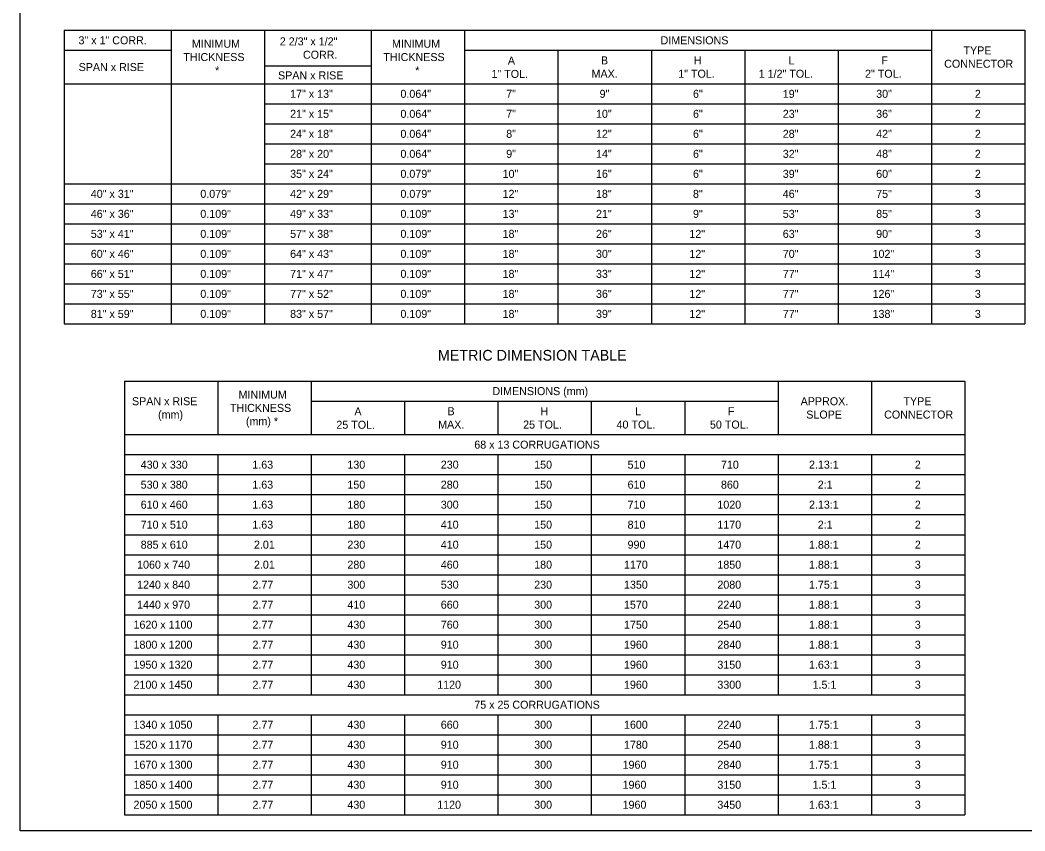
# Model space of a CAD drawing. Extents: x 49991.4 to 50021, y 49987.6 to 50011.4.
# Drawn here: x 49999.38 to 50006.92, y 49987.8 to 49993.88 of the extents above; entities that cross this region are included whole.
import ezdxf

# ---------------------------------------------------------------- set-up
doc = ezdxf.new("R2010")
doc.units = 0
doc.layers.add('Level 1', color=7, linetype='Continuous')
doc.layers.add('Level 2', color=7, linetype='Continuous')

msp = doc.modelspace()

# ---------------------------------------------------------------- linework, layer by layer
at = {"layer": 'Level 1'}
msp.add_lwpolyline([(49999.3835, 49998.9992), (50016.7501, 49998.9992), (50016.7501, 49987.7988), (49999.3835, 49987.7988)], close=True, dxfattribs=at)
at = {"layer": 'Level 2'}
for p, q in [((49999.715, 49993.802), (50006.915, 49993.802)), ((49999.715, 49993.802), (50006.915, 49993.802)), ((49999.715, 49993.802), (49999.715, 49991.6007)), ((50000.515, 49993.802), (50000.515, 49991.6007)), ((50001.215, 49993.802), (50001.215, 49991.6007)), ((50002.015, 49993.802), (50002.015, 49991.6007)), ((50002.715, 49993.802), (50002.715, 49993.2507)), ((50002.715, 49993.802), (50002.715, 49993.2507)), ((50006.215, 49993.802), (50006.215, 49993.2507)), ((50006.215, 49993.802), (50006.215, 49993.2507)), ((50006.915, 49993.802), (50006.915, 49993.402)), ((50006.915, 49993.802), (50006.915, 49993.402)), ((50006.915, 49993.802), (50006.915, 49991.6007)), ((49999.715, 49993.652), (50000.515, 49993.652)), ((50002.715, 49993.652), (50006.215, 49993.652)), ((50003.415, 49993.652), (50003.415, 49993.402)), ((50003.415, 49993.652), (50003.415, 49993.402)), ((50004.115, 49993.652), (50004.115, 49993.402)), ((50004.115, 49993.652), (50004.115, 49993.402)), ((50004.815, 49993.652), (50004.815, 49993.2507)), ((50004.815, 49993.652), (50004.815, 49993.2507)), ((50005.515, 49993.652), (50005.515, 49993.402)), ((50005.515, 49993.652), (50005.515, 49993.402)), ((50001.215, 49993.5351), (50002.015, 49993.5351)), ((49999.715, 49993.4007), (50006.915, 49993.4007)), ((49999.715, 49993.4007), (50006.915, 49993.4007)), ((50003.415, 49993.4007), (50003.415, 49991.6007)), ((50004.115, 49993.4007), (50004.115, 49991.6007)), ((50005.515, 49993.4007), (50005.515, 49991.6007)), ((50001.215, 49993.2507), (50006.915, 49993.2507)), ((50002.715, 49993.2507), (50002.715, 49991.6007)), ((50004.815, 49993.2507), (50004.815, 49991.6007)), ((50006.215, 49993.2507), (50006.215, 49991.6007)), ((50006.215, 49993.2507), (50006.215, 49991.6007)), ((50001.215, 49993.1007), (50006.915, 49993.1007)), ((50001.215, 49992.9507), (50006.915, 49992.9507)), ((50001.215, 49992.8007), (50006.915, 49992.8007)), ((49999.715, 49992.6507), (50006.915, 49992.6507)), ((49999.715, 49992.6507), (50006.915, 49992.6507)), ((49999.715, 49992.5007), (50006.915, 49992.5007)), ((49999.715, 49992.5007), (50006.915, 49992.5007)), ((49999.715, 49992.3507), (50006.915, 49992.3507)), ((49999.715, 49992.3507), (50006.915, 49992.3507)), ((49999.715, 49992.2007), (50006.915, 49992.2007)), ((49999.715, 49992.2007), (50006.915, 49992.2007)), ((49999.715, 49992.0507), (50006.915, 49992.0507)), ((49999.715, 49992.0507), (50006.915, 49992.0507)), ((49999.715, 49991.9007), (50006.915, 49991.9007)), ((49999.715, 49991.9007), (50006.915, 49991.9007)), ((49999.715, 49991.7507), (50006.915, 49991.7507)), ((49999.715, 49991.7507), (50006.915, 49991.7507)), ((49999.715, 49991.6007), (50006.915, 49991.6007)), ((50000.165, 49991.1714), (50006.465, 49991.1714)), ((50000.165, 49991.1714), (50000.165, 49987.9201)), ((50000.865, 49991.1714), (50000.865, 49990.7714)), ((50001.565, 49991.1714), (50001.565, 49990.7714)), ((50005.065, 49991.1714), (50005.065, 49990.7714)), ((50005.765, 49991.1714), (50005.765, 49990.7714)), ((50006.465, 49991.1714), (50006.465, 49987.9201)), ((50001.565, 49991.0214), (50005.065, 49991.0214)), ((50002.265, 49991.0214), (50002.265, 49990.7714)), ((50002.965, 49991.0214), (50002.965, 49990.7714)), ((50003.665, 49991.0214), (50003.665, 49990.7714)), ((50004.365, 49991.0214), (50004.365, 49990.7714)), ((50000.165, 49990.7701), (50006.465, 49990.7701)), ((50000.165, 49990.6201), (50006.465, 49990.6201)), ((50000.865, 49990.6201), (50000.865, 49988.8201)), ((50001.565, 49990.6201), (50001.565, 49988.8201)), ((50002.265, 49990.6201), (50002.265, 49988.8201)), ((50002.965, 49990.6201), (50002.965, 49988.8201)), ((50003.665, 49990.6201), (50003.665, 49988.8201)), ((50004.365, 49990.6201), (50004.365, 49988.8201)), ((50005.065, 49990.6201), (50005.065, 49988.8201)), ((50005.765, 49990.6201), (50005.765, 49988.8201)), ((50000.165, 49990.4701), (50006.465, 49990.4701)), ((50000.165, 49990.3201), (50006.465, 49990.3201)), ((50000.165, 49990.1701), (50006.465, 49990.1701)), ((50000.165, 49990.0201), (50006.465, 49990.0201)), ((50000.165, 49989.8701), (50006.465, 49989.8701)), ((50000.165, 49989.7201), (50006.465, 49989.7201)), ((50000.165, 49989.5701), (50006.465, 49989.5701)), ((50000.165, 49989.4201), (50006.465, 49989.4201)), ((50000.165, 49989.2701), (50006.465, 49989.2701)), ((50000.165, 49989.1201), (50006.465, 49989.1201)), ((50000.165, 49988.9701), (50006.465, 49988.9701)), ((50000.165, 49988.8201), (50006.465, 49988.8201)), ((50000.165, 49988.6701), (50006.465, 49988.6701)), ((50000.865, 49988.6701), (50000.865, 49987.9201)), ((50001.565, 49988.6701), (50001.565, 49987.9201)), ((50002.265, 49988.6701), (50002.265, 49987.9201)), ((50002.965, 49988.6701), (50002.965, 49987.9201)), ((50003.665, 49988.6701), (50003.665, 49987.9201)), ((50004.365, 49988.6701), (50004.365, 49987.9201)), ((50005.065, 49988.6701), (50005.065, 49987.9201)), ((50005.765, 49988.6701), (50005.765, 49987.9201)), ((50000.165, 49988.5201), (50006.465, 49988.5201)), ((50000.165, 49988.3701), (50006.465, 49988.3701)), ((50000.165, 49988.2201), (50006.465, 49988.2201)), ((50000.165, 49988.0701), (50006.465, 49988.0701)), ((50000.165, 49987.9201), (50006.465, 49987.9201))]:
    msp.add_line(p, q, dxfattribs=at)

# ---------------------------------------------------------------- texts
for s, height, p in [('3" x 1" CORR.', 0.06, (49999.8211, 49993.697)), ('MINIMUM', 0.06, (50000.671, 49993.6713)), ('2 2/3" x 1/2"', 0.06, (50001.3303, 49993.6888)), ('MINIMUM', 0.06, (50002.171, 49993.6713)), ('DIMENSIONS', 0.06, (50004.1845, 49993.697)), ('THICKNESS', 0.06, (50000.6065, 49993.5713)), ('CORR.', 0.06, (50001.5038, 49993.5888)), ('THICKNESS', 0.06, (50002.1065, 49993.5713)), ('TYPE', 0.06, (50006.4549, 49993.6213)), ('SPAN x RISE', 0.06, (49999.8223, 49993.4963)), ('A', 0.06, (50003.0393, 49993.5448)), ('B', 0.06, (50003.7374, 49993.5463)), ('H', 0.06, (50004.433, 49993.5463)), ('L', 0.06, (50005.1438, 49993.5463)), ('F', 0.06, (50005.8388, 49993.5463)), ('CONNECTOR', 0.06, (50006.3099, 49993.5213)), ('*', 0.06, (50000.8451, 49993.4713)), ('SPAN x RISE', 0.06, (50001.3168, 49993.4341)), ('*', 0.06, (50002.3451, 49993.4713)), ('1" TOL.', 0.06, (50002.9168, 49993.4448)), ('MAX.', 0.06, (50003.6669, 49993.4463)), ('1" TOL.', 0.06, (50004.3168, 49993.4463)), ('1 1/2" TOL.', 0.06, (50004.9201, 49993.4463)), ('2" TOL.', 0.06, (50005.7168, 49993.4463)), ('17" x 13"', 0.06, (50001.4075, 49993.2957)), ('0.064"', 0.06, (50002.2344, 49993.2957)), ('7"', 0.06, (50003.0271, 49993.2957)), ('9"', 0.06, (50003.7271, 49993.2957)), ('6"', 0.06, (50004.4271, 49993.2957)), ('19"', 0.06, (50005.1001, 49993.2957)), ('30"', 0.06, (50005.8001, 49993.2957)), ('2', 0.06, (50006.5399, 49993.2957)), ('21" x 15"', 0.06, (50001.4075, 49993.1457)), ('0.064"', 0.06, (50002.2344, 49993.1457)), ('7"', 0.06, (50003.0271, 49993.1457)), ('10"', 0.06, (50003.7001, 49993.1457)), ('6"', 0.06, (50004.4271, 49993.1457)), ('23"', 0.06, (50005.1001, 49993.1457)), ('36"', 0.06, (50005.8001, 49993.1457)), ('2', 0.06, (50006.5399, 49993.1457)), ('2', 0.06, (50006.5399, 49993.1457)), ('24" x 18"', 0.06, (50001.4075, 49992.9957)), ('0.064"', 0.06, (50002.2344, 49992.9957)), ('8"', 0.06, (50003.0271, 49992.9957)), ('12"', 0.06, (50003.7001, 49992.9957)), ('6"', 0.06, (50004.4271, 49992.9957)), ('28"', 0.06, (50005.1001, 49992.9957)), ('42"', 0.06, (50005.8001, 49992.9957)), ('2', 0.06, (50006.5399, 49992.9957)), ('2', 0.06, (50006.5399, 49992.9957)), ('28" x 20"', 0.06, (50001.4075, 49992.8457)), ('0.064"', 0.06, (50002.2344, 49992.8457)), ('9"', 0.06, (50003.0271, 49992.8457)), ('14"', 0.06, (50003.7001, 49992.8457)), ('6"', 0.06, (50004.4271, 49992.8457)), ('32"', 0.06, (50005.1001, 49992.8457)), ('48"', 0.06, (50005.8001, 49992.8457)), ('2', 0.06, (50006.5399, 49992.8457)), ('2', 0.06, (50006.5399, 49992.8457)), ('35" x 24"', 0.06, (50001.4075, 49992.6957)), ('0.079"', 0.06, (50002.2344, 49992.6957)), ('10"', 0.06, (50003.0001, 49992.6957)), ('16"', 0.06, (50003.7001, 49992.6957)), ('6"', 0.06, (50004.4271, 49992.6957)), ('39"', 0.06, (50005.1001, 49992.6957)), ('60"', 0.06, (50005.8001, 49992.6957)), ('2', 0.06, (50006.5399, 49992.6957)), ('2', 0.06, (50006.5399, 49992.6957)), ('40" x 31"', 0.06, (49999.9134, 49992.5457)), ('40" x 31"', 0.06, (49999.9134, 49992.5457)), ('0.079"', 0.06, (50000.7344, 49992.5457)), ('42" x 29"', 0.06, (50001.4075, 49992.5457)), ('0.079"', 0.06, (50002.2344, 49992.5457)), ('12"', 0.06, (50003.0001, 49992.5457)), ('18"', 0.06, (50003.7001, 49992.5457)), ('8"', 0.06, (50004.4271, 49992.5457)), ('46"', 0.06, (50005.1001, 49992.5457)), ('75"', 0.06, (50005.8001, 49992.5457)), ('3', 0.06, (50006.5398, 49992.5457)), ('3', 0.06, (50006.5398, 49992.5457)), ('46" x 36"', 0.06, (49999.9134, 49992.3957)), ('0.109"', 0.06, (50000.7344, 49992.3957)), ('49" x 33"', 0.06, (50001.4075, 49992.3957)), ('0.109"', 0.06, (50002.2344, 49992.3957)), ('13"', 0.06, (50003.0001, 49992.3957)), ('21"', 0.06, (50003.7001, 49992.3957)), ('9"', 0.06, (50004.4271, 49992.3957)), ('53"', 0.06, (50005.1001, 49992.3957)), ('85"', 0.06, (50005.8001, 49992.3957)), ('3', 0.06, (50006.5398, 49992.3957)), ('3', 0.06, (50006.5398, 49992.3957)), ('53" x 41"', 0.06, (49999.9134, 49992.2457)), ('0.109"', 0.06, (50000.7344, 49992.2457)), ('57" x 38"', 0.06, (50001.4075, 49992.2457)), ('0.109"', 0.06, (50002.2344, 49992.2457)), ('18"', 0.06, (50003.0001, 49992.2457)), ('26"', 0.06, (50003.7001, 49992.2457)), ('12"', 0.06, (50004.4001, 49992.2457)), ('63"', 0.06, (50005.1001, 49992.2457)), ('90"', 0.06, (50005.8001, 49992.2457)), ('3', 0.06, (50006.5398, 49992.2457)), ('3', 0.06, (50006.5398, 49992.2457)), ('60" x 46"', 0.06, (49999.9134, 49992.0957)), ('0.109"', 0.06, (50000.7344, 49992.0957)), ('64" x 43"', 0.06, (50001.4075, 49992.0957)), ('0.109"', 0.06, (50002.2344, 49992.0957)), ('18"', 0.06, (50003.0001, 49992.0957)), ('30"', 0.06, (50003.7001, 49992.0957)), ('12"', 0.06, (50004.4001, 49992.0957)), ('70"', 0.06, (50005.1001, 49992.0957)), ('102"', 0.06, (50005.7732, 49992.0957)), ('3', 0.06, (50006.5398, 49992.0957)), ('3', 0.06, (50006.5398, 49992.0957)), ('66" x 51"', 0.06, (49999.9134, 49991.9457)), ('0.109"', 0.06, (50000.7344, 49991.9457)), ('71" x 47"', 0.06, (50001.4075, 49991.9457)), ('0.109"', 0.06, (50002.2344, 49991.9457)), ('18"', 0.06, (50003.0001, 49991.9457)), ('33"', 0.06, (50003.7001, 49991.9457)), ('12"', 0.06, (50004.4001, 49991.9457)), ('77"', 0.06, (50005.1001, 49991.9457)), ('114"', 0.06, (50005.7732, 49991.9457)), ('3', 0.06, (50006.5398, 49991.9457)), ('3', 0.06, (50006.5398, 49991.9457)), ('73" x 55"', 0.06, (49999.9134, 49991.7957)), ('0.109"', 0.06, (50000.7344, 49991.7957)), ('77" x 52"', 0.06, (50001.4075, 49991.7957)), ('0.109"', 0.06, (50002.2344, 49991.7957)), ('18"', 0.06, (50003.0001, 49991.7957)), ('36"', 0.06, (50003.7001, 49991.7957)), ('12"', 0.06, (50004.4001, 49991.7957)), ('77"', 0.06, (50005.1001, 49991.7957)), ('126"', 0.06, (50005.7732, 49991.7957)), ('3', 0.06, (50006.5398, 49991.7957)), ('3', 0.06, (50006.5398, 49991.7957)), ('81" x 59"', 0.06, (49999.9134, 49991.6457)), ('0.109"', 0.06, (50000.7344, 49991.6457)), ('83" x 57"', 0.06, (50001.4075, 49991.6457)), ('0.109"', 0.06, (50002.2344, 49991.6457)), ('18"', 0.06, (50003.0001, 49991.6457)), ('39"', 0.06, (50003.7001, 49991.6457)), ('12"', 0.06, (50004.4001, 49991.6457)), ('77"', 0.06, (50005.1001, 49991.6457)), ('138"', 0.06, (50005.7732, 49991.6457)), ('3', 0.06, (50006.5398, 49991.6457)), ('3', 0.06, (50006.5398, 49991.6457)), ('METRIC DIMENSION TABLE', 0.08, (50002.5156, 49991.3255)), ('DIMENSIONS (mm)', 0.06, (50002.9237, 49991.0665)), ('MINIMUM', 0.06, (50001.021, 49991.0407)), ('SPAN x RISE', 0.06, (50000.2221, 49990.9907)), ('THICKNESS', 0.06, (50000.9565, 49990.9407)), ('APPROX.', 0.06, (50005.2343, 49990.9907)), ('TYPE', 0.06, (50006.0049, 49990.9907)), ('(mm)', 0.06, (50000.4177, 49990.8907)), ('(mm) *', 0.06, (50001.0762, 49990.8407)), ('A', 0.06, (50001.8893, 49990.9142)), ('B', 0.06, (50002.5874, 49990.9157)), ('H', 0.06, (50003.283, 49990.9157)), ('L', 0.06, (50003.9938, 49990.9157)), ('F', 0.06, (50004.6888, 49990.9157)), ('SLOPE', 0.06, (50005.2762, 49990.8907)), ('CONNECTOR', 0.06, (50005.8599, 49990.8907)), ('25 TOL.', 0.06, (50001.7542, 49990.8142)), ('MAX.', 0.06, (50002.5169, 49990.8157)), ('25 TOL.', 0.06, (50003.1542, 49990.8157)), ('40 TOL.', 0.06, (50003.8542, 49990.8157)), ('50 TOL.', 0.06, (50004.5542, 49990.8157)), ('68 x 13 CORRUGATIONS', 0.06, (50002.7879, 49990.6651)), ('430 x 330', 0.06, (50000.2874, 49990.5151)), ('1.63', 0.06, (50001.1241, 49990.5151)), ('130', 0.06, (50001.8368, 49990.5151)), ('230', 0.06, (50002.5368, 49990.5151)), ('150', 0.06, (50003.2368, 49990.5151)), ('510', 0.06, (50003.9368, 49990.5151)), ('710', 0.06, (50004.6368, 49990.5151)), ('2.13:1', 0.06, (50005.2965, 49990.5151)), ('2', 0.06, (50006.0899, 49990.5151)), ('530 x 380', 0.06, (50000.2874, 49990.3651)), ('1.63', 0.06, (50001.1241, 49990.3651)), ('150', 0.06, (50001.8368, 49990.3651)), ('280', 0.06, (50002.5368, 49990.3651)), ('150', 0.06, (50003.2368, 49990.3651)), ('610', 0.06, (50003.9368, 49990.3651)), ('860', 0.06, (50004.6368, 49990.3651)), ('2:1', 0.06, (50005.3622, 49990.3651)), ('2', 0.06, (50006.0899, 49990.3651)), ('610 x 460', 0.06, (50000.2874, 49990.2151)), ('1.63', 0.06, (50001.1241, 49990.2151)), ('180', 0.06, (50001.8368, 49990.2151)), ('300', 0.06, (50002.5368, 49990.2151)), ('150', 0.06, (50003.2368, 49990.2151)), ('710', 0.06, (50003.9368, 49990.2151)), ('1020', 0.06, (50004.6099, 49990.2151)), ('2.13:1', 0.06, (50005.2965, 49990.2151)), ('2', 0.06, (50006.0899, 49990.2151)), ('710 x 510', 0.06, (50000.2874, 49990.0651)), ('1.63', 0.06, (50001.1241, 49990.0651)), ('180', 0.06, (50001.8368, 49990.0651)), ('410', 0.06, (50002.5368, 49990.0651)), ('150', 0.06, (50003.2368, 49990.0651)), ('810', 0.06, (50003.9368, 49990.0651)), ('1170', 0.06, (50004.6099, 49990.0651)), ('2:1', 0.06, (50005.3622, 49990.0651)), ('2', 0.06, (50006.0899, 49990.0651)), ('885 x 610', 0.06, (50000.2874, 49989.9151)), ('2.01', 0.06, (50001.1364, 49989.9151)), ('230', 0.06, (50001.8368, 49989.9151)), ('410', 0.06, (50002.5368, 49989.9151)), ('150', 0.06, (50003.2368, 49989.9151)), ('990', 0.06, (50003.9368, 49989.9151)), ('1470', 0.06, (50004.6099, 49989.9151)), ('1.88:1', 0.06, (50005.2965, 49989.9151)), ('2', 0.06, (50006.0899, 49989.9151)), ('1060 x 740', 0.06, (50000.2605, 49989.7651)), ('2.01', 0.06, (50001.1364, 49989.7651)), ('280', 0.06, (50001.8368, 49989.7651)), ('460', 0.06, (50002.5368, 49989.7651)), ('180', 0.06, (50003.2368, 49989.7651)), ('1170', 0.06, (50003.9099, 49989.7651)), ('1850', 0.06, (50004.6099, 49989.7651)), ('1.88:1', 0.06, (50005.2965, 49989.7651)), ('3', 0.06, (50006.0898, 49989.7651)), ('1240 x 840', 0.06, (50000.2605, 49989.6151)), ('2.77', 0.06, (50001.1255, 49989.6151)), ('300', 0.06, (50001.8368, 49989.6151)), ('530', 0.06, (50002.5368, 49989.6151)), ('230', 0.06, (50003.2368, 49989.6151)), ('1350', 0.06, (50003.9099, 49989.6151)), ('2080', 0.06, (50004.6099, 49989.6151)), ('1.75:1', 0.06, (50005.2965, 49989.6151)), ('3', 0.06, (50006.0898, 49989.6151)), ('1440 x 970', 0.06, (50000.2605, 49989.4651)), ('2.77', 0.06, (50001.1255, 49989.4651)), ('410', 0.06, (50001.8368, 49989.4651)), ('660', 0.06, (50002.5368, 49989.4651)), ('300', 0.06, (50003.2368, 49989.4651)), ('1570', 0.06, (50003.9099, 49989.4651)), ('2240', 0.06, (50004.6099, 49989.4651)), ('1.88:1', 0.06, (50005.2965, 49989.4651)), ('3', 0.06, (50006.0898, 49989.4651)), ('1620 x 1100', 0.06, (50000.2336, 49989.3151)), ('2.77', 0.06, (50001.1255, 49989.3151)), ('430', 0.06, (50001.8368, 49989.3151)), ('760', 0.06, (50002.5368, 49989.3151)), ('300', 0.06, (50003.2368, 49989.3151)), ('1750', 0.06, (50003.9099, 49989.3151)), ('2540', 0.06, (50004.6099, 49989.3151)), ('1.88:1', 0.06, (50005.2965, 49989.3151)), ('3', 0.06, (50006.0898, 49989.3151)), ('1800 x 1200', 0.06, (50000.2336, 49989.1651)), ('2.77', 0.06, (50001.1255, 49989.1651)), ('430', 0.06, (50001.8368, 49989.1651)), ('910', 0.06, (50002.5368, 49989.1651)), ('300', 0.06, (50003.2368, 49989.1651)), ('1960', 0.06, (50003.9099, 49989.1651)), ('2840', 0.06, (50004.6099, 49989.1651)), ('1.88:1', 0.06, (50005.2965, 49989.1651)), ('3', 0.06, (50006.0898, 49989.1651)), ('1950 x 1320', 0.06, (50000.2336, 49989.0151)), ('2.77', 0.06, (50001.1255, 49989.0151)), ('430', 0.06, (50001.8368, 49989.0151)), ('910', 0.06, (50002.5368, 49989.0151)), ('300', 0.06, (50003.2368, 49989.0151)), ('1960', 0.06, (50003.9099, 49989.0151)), ('3150', 0.06, (50004.6099, 49989.0151)), ('1.63:1', 0.06, (50005.2965, 49989.0151)), ('3', 0.06, (50006.0898, 49989.0151)), ('2100 x 1450', 0.06, (50000.2336, 49988.8651)), ('2.77', 0.06, (50001.1255, 49988.8651)), ('430', 0.06, (50001.8368, 49988.8651)), ('1120', 0.06, (50002.5099, 49988.8651)), ('300', 0.06, (50003.2368, 49988.8651)), ('1960', 0.06, (50003.9099, 49988.8651)), ('3300', 0.06, (50004.6099, 49988.8651)), ('1.5:1', 0.06, (50005.3234, 49988.8651)), ('3', 0.06, (50006.0898, 49988.8651)), ('75 x 25 CORRUGATIONS', 0.06, (50002.7879, 49988.7151)), ('1340 x 1050', 0.06, (50000.2336, 49988.5651)), ('2.77', 0.06, (50001.1255, 49988.5651)), ('430', 0.06, (50001.8368, 49988.5651)), ('660', 0.06, (50002.5368, 49988.5651)), ('300', 0.06, (50003.2368, 49988.5651)), ('1600', 0.06, (50003.9099, 49988.5651)), ('2240', 0.06, (50004.6099, 49988.5651)), ('1.75:1', 0.06, (50005.2965, 49988.5651)), ('3', 0.06, (50006.0898, 49988.5651)), ('1520 x 1170', 0.06, (50000.2336, 49988.4151)), ('2.77', 0.06, (50001.1255, 49988.4151)), ('430', 0.06, (50001.8368, 49988.4151)), ('910', 0.06, (50002.5368, 49988.4151)), ('300', 0.06, (50003.2368, 49988.4151)), ('1780', 0.06, (50003.9099, 49988.4151)), ('2540', 0.06, (50004.6099, 49988.4151)), ('1.88:1', 0.06, (50005.2965, 49988.4151)), ('3', 0.06, (50006.0898, 49988.4151)), ('1670 x 1300', 0.06, (50000.2336, 49988.2651)), ('2.77', 0.06, (50001.1255, 49988.2651)), ('430', 0.06, (50001.8368, 49988.2651)), ('910', 0.06, (50002.5368, 49988.2651)), ('300', 0.06, (50003.2368, 49988.2651)), ('1960', 0.06, (50003.8994, 49988.2651)), ('2840', 0.06, (50004.6099, 49988.2651)), ('1.75:1', 0.06, (50005.2965, 49988.2651)), ('3', 0.06, (50006.0898, 49988.2651)), ('1850 x 1400', 0.06, (50000.2336, 49988.1151)), ('2.77', 0.06, (50001.1255, 49988.1151)), ('430', 0.06, (50001.8368, 49988.1151)), ('910', 0.06, (50002.5368, 49988.1151)), ('300', 0.06, (50003.2368, 49988.1151)), ('1960', 0.06, (50003.8994, 49988.1151)), ('3150', 0.06, (50004.6099, 49988.1151)), ('1.5:1', 0.06, (50005.3234, 49988.1151)), ('3', 0.06, (50006.0898, 49988.1151)), ('2050 x 1500', 0.06, (50000.2336, 49987.9651)), ('2.77', 0.06, (50001.1255, 49987.9651)), ('430', 0.06, (50001.8368, 49987.9651)), ('1120', 0.06, (50002.5099, 49987.9651)), ('300', 0.06, (50003.2368, 49987.9651)), ('1960', 0.06, (50003.8994, 49987.9651)), ('3450', 0.06, (50004.6099, 49987.9651)), ('1.63:1', 0.06, (50005.2965, 49987.9651)), ('3', 0.06, (50006.0898, 49987.9651))]:
    msp.add_text(s, height=height, dxfattribs=at).set_placement(p)

doc.saveas('drawing.dxf')
